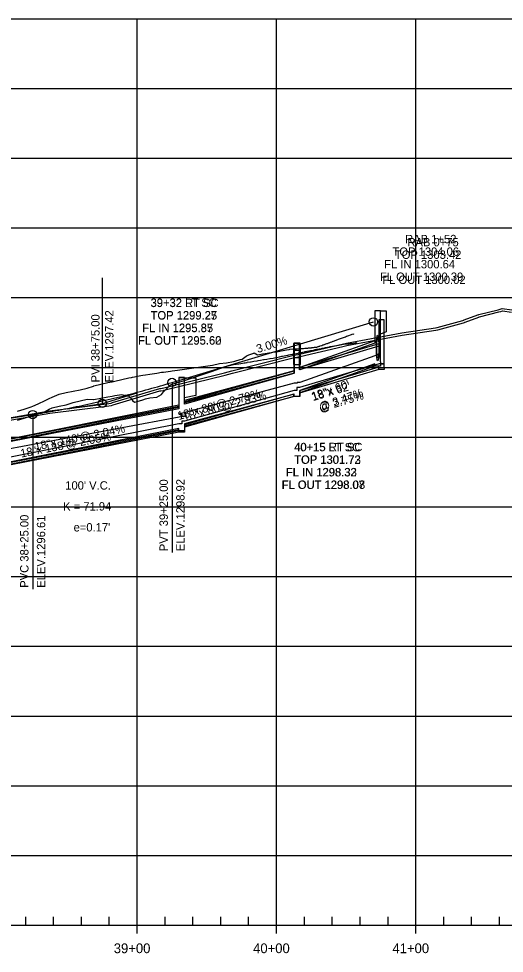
# Model space of a CAD drawing. Extents: x 670877 to 686811, y 705985 to 708501.
# Drawn here: x 685288 to 685636, y 707018 to 707688 of the extents above; entities that cross this region are included whole.
import ezdxf

# ---------------------------------------------------------------- set-up
doc = ezdxf.new("R2010")
doc.units = 0
for name, color, linetype in [('30', 7, 'Continuous'), ('37', 7, 'Continuous'), ('DRAINAGE_HGL LEFT', 7, 'Continuous'), ('DRAINAGE_HGL RIGHT', 7, 'Continuous'), ('Profile Drainage Annot Left', 7, 'Continuous'), ('Profile Drainage Annot Right', 7, 'Continuous'), ('R_Drainage Extensions_RIGHT', 7, 'Continuous'), ('R_Drainage LEFT', 7, 'Continuous'), ('R_Drainage RIGHT', 7, 'Continuous'), ('R_Exist Surface', 7, 'Continuous'), ('R_Profile Work Left', 7, 'Continuous'), ('R_Profile Work Right', 7, 'Continuous'), ('R_Vert Alg', 7, 'Continuous'), ('R_Vert Alg Annot', 7, 'Continuous')]:
    doc.layers.add(name, color=color, linetype=linetype)

msp = doc.modelspace()

# ---------------------------------------------------------------- linework, layer by layer
at = {"layer": '37'}
for p, q in [((684473.03, 707688.43), (686573.03, 707688.43)), ((685373.03, 707038.43), (685373.03, 707688.43)), ((685473.03, 707038.43), (685473.03, 707688.43)), ((685573.03, 707038.43), (685573.03, 707688.43)), ((684473.03, 707638.43), (686573.03, 707638.43)), ((684473.03, 707588.43), (686573.03, 707588.43)), ((684473.03, 707538.43), (686573.03, 707538.43)), ((684473.03, 707488.43), (686573.03, 707488.43)), ((684473.03, 707438.43), (686573.03, 707438.43)), ((684473.03, 707388.43), (686573.03, 707388.43)), ((684473.03, 707338.43), (686573.03, 707338.43)), ((684473.03, 707288.43), (686573.03, 707288.43)), ((684473.03, 707238.43), (686573.03, 707238.43)), ((684473.03, 707188.43), (686573.03, 707188.43)), ((684473.03, 707138.43), (686573.03, 707138.43)), ((684473.03, 707088.43), (686573.03, 707088.43)), ((685293.03, 707038.43), (685293.03, 707044.43)), ((685313.03, 707038.43), (685313.03, 707044.43)), ((685333.03, 707038.43), (685333.03, 707044.43)), ((685353.03, 707038.43), (685353.03, 707044.43)), ((685393.03, 707038.43), (685393.03, 707044.43)), ((685413.03, 707038.43), (685413.03, 707044.43)), ((685433.03, 707038.43), (685433.03, 707044.43)), ((685453.03, 707038.43), (685453.03, 707044.43)), ((685493.03, 707038.43), (685493.03, 707044.43)), ((685513.03, 707038.43), (685513.03, 707044.43)), ((685533.03, 707038.43), (685533.03, 707044.43)), ((685553.03, 707038.43), (685553.03, 707044.43)), ((685593.03, 707038.43), (685593.03, 707044.43)), ((685613.03, 707038.43), (685613.03, 707044.43)), ((685633.03, 707038.43), (685633.03, 707044.43)), ((684473.03, 707038.43), (686573.03, 707038.43)), ((685373.03, 707032.43), (685373.03, 707038.43)), ((685473.03, 707032.43), (685473.03, 707038.43)), ((685573.03, 707032.43), (685573.03, 707038.43))]:
    msp.add_line(p, q, dxfattribs=at)
at = {"layer": 'DRAINAGE_HGL LEFT'}
for points in [[(685263.31, 707399.22), (685310, 707407.29), (685350.89, 707412.31), (685354.24, 707412.73), (685355.27, 707413.16), (685389.24, 707423.35), (685389.91, 707423.25), (685391.03, 707423.48), (685391.17, 707423.64), (685435.74, 707434.43), (685440.97, 707435.87), (685484.53, 707446.95), (685489.61, 707447.94), (685520.16, 707454.98), (685523.19, 707455.67), (685559.03, 707462.39), (685563.01, 707463.18), (685587.1, 707466.75), (685588.11, 707466.94), (685588.32, 707467.01), (685606.77, 707472.02), (685607.18, 707472.18), (685607.55, 707472.34), (685607.76, 707472.44), (685617.53, 707476.03), (685617.73, 707476.1), (685618.13, 707476.31), (685632.15, 707479.78), (685633.61, 707480.15), (685634.93, 707480.62), (685641.88, 707479.61)], [(685548.38, 707441), (685550.38, 707441), (685550.38, 707441), (685546.6, 707441), (685489.4, 707424), (685487.48, 707424), (685487.48, 707421.93), (685485.57, 707421.93), (685407.03, 707399.93), (685405.03, 707399.93), (685405.03, 707398.05), (685403.03, 707398.05), (685258.95, 707369.45), (685260.95, 707369.45), (685260.95, 707368.25), (685262.95, 707368.25), (685115.94, 707349.55), (685117.94, 707349.55)]]:
    msp.add_lwpolyline(points, dxfattribs=at)
at = {"layer": 'DRAINAGE_HGL RIGHT'}
msp.add_lwpolyline([(685545.7, 707448.17), (685547.73, 707448.17), (685547.73, 707448.17), (685547.73, 707448.17), (685489.71, 707427.57), (685487.73, 707427.57), (685487.73, 707427.18), (685485.75, 707427.18), (685403.03, 707404.88), (685405.03, 707404.88), (685405.03, 707403.45), (685407.03, 707403.45), (685261.02, 707376.21), (685263.02, 707376.21), (685263.02, 707376.21), (685265.02, 707376.21), (685120.97, 707361.92), (685121.24, 707355.66), (685097.92, 707346.66)], dxfattribs=at)
at = {"layer": 'R_Drainage Extensions_RIGHT'}
msp.add_lwpolyline([(685547.73, 707479.03), (685551.73, 707479.03), (685551.73, 707464.03), (685547.73, 707462.36), (685547.73, 707479.03)], dxfattribs=at)
at = {"layer": 'R_Drainage LEFT'}
for points in [[(685550.38, 707472.63), (685546.38, 707472.63)], [(685546.38, 707472.63), (685546.38, 707453.56)], [(685550.38, 707438.63), (685550.38, 707472.63)], [(685489.48, 707455.63), (685485.48, 707455.63)], [(685485.48, 707455.63), (685485.48, 707434.11)], [(685489.48, 707436.65), (685489.48, 707455.63)], [(685546.38, 707455.23), (685489.48, 707438.32)], [(685546.38, 707453.56), (685489.48, 707436.65)], [(685546.38, 707438.56), (685489.48, 707421.65)], [(685546.38, 707436.9), (685546.38, 707438.56)], [(685550.38, 707438.63), (685550.38, 707436.9)], [(685407.03, 707431.13), (685403.03, 707431.13)], [(685403.03, 707431.13), (685403.03, 707409.63)], [(685485.48, 707435.77), (685407.03, 707413.8)], [(685485.48, 707434.11), (685407.03, 707412.13)], [(685407.03, 707412.13), (685407.03, 707431.13)], [(685546.38, 707436.9), (685489.48, 707419.99)], [(685550.38, 707436.9), (685546.38, 707436.9)], [(685485.48, 707419.11), (685407.03, 707397.13)], [(685485.48, 707417.44), (685407.03, 707395.46)], [(685485.48, 707417.44), (685485.48, 707419.11)], [(685489.48, 707417.44), (685485.48, 707417.44)], [(685489.48, 707421.65), (685489.48, 707417.44)], [(685403.03, 707411.3), (685262.95, 707383.49)], [(685403.03, 707409.63), (685262.95, 707381.82)], [(685407.03, 707397.13), (685407.03, 707392.96)], [(685403.03, 707394.63), (685262.95, 707366.82)], [(685403.03, 707392.96), (685262.95, 707365.16)], [(685403.03, 707392.96), (685403.03, 707394.63)], [(685407.03, 707392.96), (685403.03, 707392.96)]]:
    msp.add_lwpolyline(points, dxfattribs=at)
at = {"layer": 'R_Drainage RIGHT'}
for points in [[(685547.73, 707479.03), (685543.68, 707479.03)], [(685543.68, 707479.03), (685543.68, 707455.89)], [(685547.73, 707442.33), (685547.73, 707479.03)], [(685543.68, 707457.56), (685489.73, 707438.4)], [(685489.73, 707455.73), (685485.73, 707455.73)], [(685485.73, 707455.73), (685485.73, 707434.22)], [(685543.68, 707455.89), (685489.73, 707436.74)], [(685489.73, 707436.74), (685489.73, 707455.73)], [(685543.68, 707440.89), (685489.73, 707421.74)], [(685543.68, 707439.22), (685489.73, 707420.07)], [(685543.68, 707439.22), (685543.68, 707440.89)], [(685547.73, 707439.22), (685543.68, 707439.22)], [(685547.73, 707442.33), (685547.73, 707439.22)], [(685407.03, 707430.92), (685403.03, 707430.92)], [(685403.03, 707430.92), (685403.03, 707408.65)], [(685485.73, 707435.89), (685407.03, 707414.67)], [(685485.73, 707434.22), (685407.03, 707413.01)], [(685407.03, 707413.01), (685407.03, 707430.92)], [(685407.03, 707430.92), (685415.03, 707430.92), (685415.03, 707418.17), (685407.03, 707416.5), (685407.03, 707430.92)], [(685485.73, 707419.22), (685407.03, 707398.01)], [(685485.73, 707417.56), (685407.03, 707396.34)], [(685485.73, 707417.56), (685485.73, 707419.22)], [(685489.73, 707417.56), (685485.73, 707417.56)], [(685489.73, 707421.74), (685489.73, 707417.56)], [(685403.03, 707410.32), (685265.02, 707383.57)], [(685403.03, 707408.65), (685265.02, 707381.9)], [(685407.03, 707398.01), (685407.03, 707391.99)], [(685403.03, 707393.65), (685265.02, 707366.9)], [(685403.03, 707391.99), (685265.02, 707365.24)], [(685403.03, 707391.99), (685403.03, 707393.65)], [(685407.03, 707391.99), (685403.03, 707391.99)]]:
    msp.add_lwpolyline(points, dxfattribs=at)
for points in [[(685490.23, 707455.43), (685485.23, 707455.43), (685485.23, 707440.43), (685490.23, 707440.43)], [(685489.73, 707450.43), (685485.73, 707450.43), (685485.73, 707445.43), (685489.73, 707445.43)]]:
    msp.add_lwpolyline(points, close=True, dxfattribs=at)
for major_axis in [(0, 9.17), (0, 7.5)]:
    msp.add_ellipse((685545.7, 707452.33), major_axis=major_axis, ratio=0.1, dxfattribs=at)
at = {"layer": 'R_Exist Surface'}
msp.add_lwpolyline([(685263.59, 707397.57), (685310.24, 707405.64), (685351.09, 707410.65), (685354.67, 707411.1), (685355.83, 707411.58), (685389.37, 707421.65), (685389.96, 707421.56), (685391.92, 707421.96), (685392.08, 707422.14), (685436.16, 707432.81), (685441.4, 707434.26), (685484.9, 707445.32), (685489.96, 707446.31), (685520.53, 707453.35), (685523.53, 707454.03), (685559.35, 707460.75), (685563.3, 707461.54), (685587.38, 707465.1), (685588.54, 707465.32), (685588.8, 707465.41), (685607.29, 707470.43), (685607.83, 707470.64), (685608.26, 707470.83), (685608.41, 707470.9), (685618.12, 707474.46), (685618.4, 707474.57), (685618.72, 707474.73), (685632.55, 707478.16), (685634.1, 707478.55), (685635.1, 707478.91), (685641.64, 707477.96)], dxfattribs=at)
at = {"layer": 'R_Profile Work Left'}
for points in [[(685341.76, 707415.35), (685342.03, 707415.4), (685347.03, 707416.35), (685352.03, 707417.29), (685355.12, 707417.85), (685357.03, 707418.17), (685362.03, 707418.99), (685367.03, 707417.75), (685369.05, 707415.82), (685369.58, 707414.78), (685371.15, 707413.46), (685372.03, 707413.72), (685373.03, 707414.02), (685377.03, 707415.2), (685379.03, 707415.8), (685382.03, 707416.69), (685387.03, 707416.98), (685390.5, 707418.98), (685392.03, 707420.87), (685397.03, 707425.98), (685398.03, 707426.36), (685402.03, 707427.57), (685407.03, 707429.1), (685412.03, 707430.78), (685417.03, 707432.45), (685422.03, 707434.13), (685426.98, 707435.79), (685431.74, 707437.39), (685436.5, 707438.98), (685441.26, 707440.22), (685442.21, 707440.38), (685446, 707441.03), (685447.33, 707441.25), (685449.7, 707441.65), (685450.45, 707441.78), (685452.01, 707442.04), (685452.06, 707442.05), (685454.42, 707442.44), (685454.76, 707442.5), (685456.76, 707442.83), (685459.04, 707443.21), (685459.09, 707443.22), (685459.9, 707443.35), (685461.42, 707443.6), (685463.73, 707443.98), (685464.15, 707444.05), (685466.03, 707444.36), (685468.32, 707444.74), (685468.38, 707444.75), (685470.61, 707445.13), (685472.6, 707445.53), (685472.89, 707445.59), (685475.15, 707446.03), (685476.82, 707446.36), (685477.41, 707446.48), (685479.66, 707446.93), (685481.02, 707447.19), (685481.9, 707447.37), (685484.13, 707447.81), (685484.35, 707447.85), (685485.22, 707448.02), (685485.87, 707448.15), (685486.35, 707448.25), (685487.38, 707448.45), (685488.56, 707448.68), (685488.89, 707448.75), (685489.42, 707448.85), (685490.4, 707449.05), (685490.77, 707449.12), (685490.86, 707449.14), (685491.17, 707449.2), (685491.9, 707449.35), (685492.83, 707449.54), (685492.96, 707449.56), (685493.41, 707449.65), (685493.63, 707449.7), (685494.49, 707449.87), (685494.91, 707449.95), (685495.14, 707450), (685496.13, 707450.2), (685496.4, 707450.25), (685497.32, 707450.44), (685497.76, 707450.53), (685497.84, 707450.54), (685497.89, 707450.55), (685499.37, 707450.85), (685499.38, 707450.85), (685499.48, 707450.87), (685500.83, 707451.14), (685500.98, 707451.17), (685501.63, 707451.3), (685502.06, 707451.39), (685502.29, 707451.44), (685502.57, 707451.49), (685503.74, 707451.73), (685503.77, 707451.73), (685504.15, 707451.81), (685505.18, 707452.01), (685505.71, 707452.12), (685505.89, 707452.16), (685506.31, 707452.24), (685506.68, 707452.32), (685507.4, 707452.46), (685508.24, 707452.63), (685509.11, 707452.8), (685509.86, 707452.95), (685511.11, 707453.21), (685511.48, 707453.28), (685513.08, 707453.6), (685514.67, 707453.92), (685516.06, 707454.2), (685516.23, 707454.23), (685520.97, 707454.96), (685524.45, 707455.3), (685525.17, 707455.4), (685525.86, 707455.49), (685526.84, 707455.63), (685529.44, 707455.99), (685530.3, 707456.11), (685530.56, 707456.18)], [(685287.03, 707400.58), (685291.86, 707402.03), (685292.03, 707402.09), (685297.03, 707403.59), (685298.03, 707403.89), (685302.03, 707405.1), (685307.03, 707406.86), (685309.94, 707408.46), (685312.03, 707409.46), (685317.03, 707410.51), (685322.03, 707411.57)], [(685322.03, 707411.57), (685327.03, 707413.35), (685332.03, 707414.33), (685337.03, 707415.55), (685341.76, 707415.35)]]:
    msp.add_lwpolyline(points, dxfattribs=at)
at = {"layer": 'R_Profile Work Right'}
for points in [[(685459.36, 707447.51), (685462.03, 707447.93), (685462.09, 707447.94), (685463.03, 707448.08), (685464.81, 707448.37), (685467.53, 707448.8), (685468.03, 707448.87), (685470.25, 707449.22), (685472.96, 707449.65), (685473.03, 707449.66), (685475.42, 707450.06), (685477.53, 707450.44), (685477.83, 707450.5), (685480.23, 707450.96), (685481.99, 707451.31), (685482.62, 707451.44), (685484.98, 707451.62), (685486.41, 707451.68), (685487.32, 707451.72), (685489.65, 707451.85), (685489.88, 707451.86), (685490.6, 707451.91), (685491.13, 707451.95), (685491.53, 707451.98), (685492.37, 707452.04), (685493.33, 707452.12), (685493.59, 707452.14), (685494.02, 707452.18), (685494.8, 707452.25), (685495.09, 707452.27), (685495.17, 707452.28), (685495.42, 707452.3), (685496, 707452.36), (685496.73, 707452.42), (685496.83, 707452.43), (685497.18, 707452.47), (685497.36, 707452.49), (685498.02, 707452.56), (685498.35, 707452.6), (685498.53, 707452.62), (685499.3, 707452.71), (685499.51, 707452.73), (685500.21, 707452.82), (685500.55, 707452.86), (685500.62, 707452.87), (685500.65, 707452.87), (685501.78, 707453.01), (685501.79, 707453.02), (685501.87, 707453.03), (685502.92, 707453.32), (685503.04, 707453.36), (685503.54, 707453.53), (685503.87, 707453.64), (685504.06, 707453.71), (685504.27, 707453.78), (685505.18, 707454.09), (685505.2, 707454.1), (685505.5, 707454.2), (685506.3, 707454.48), (685506.71, 707454.62), (685506.85, 707454.67), (685507.15, 707454.77), (685507.41, 707454.86), (685507.91, 707455.04), (685508.51, 707455.25), (685509.11, 707455.46), (685509.6, 707455.64), (685510.44, 707455.94), (685510.69, 707456.02), (685511.76, 707456.41), (685512.83, 707456.8), (685513.78, 707457.15), (685513.9, 707457.19), (685518.32, 707458.84), (685521.86, 707460.17), (685522.59, 707460.44), (685523.29, 707460.7), (685524.29, 707461.07), (685526.91, 707462.05), (685527.78, 707462.38), (685528.5, 707462.34)], [(685437.03, 707441.59), (685442.03, 707442.73), (685443.03, 707442.97), (685447.03, 707443.96), (685448.42, 707444.34)], [(685448.42, 707444.34), (685451.16, 707446.54), (685452.03, 707446.88), (685453.84, 707447.58), (685453.89, 707447.61), (685456.63, 707448.67), (685457.03, 707448.83), (685459.36, 707447.51)], [(685287.03, 707407.02), (685291.86, 707408.52), (685292.03, 707408.58), (685297.03, 707410.18), (685298.03, 707410.55), (685302.03, 707412.41), (685307.03, 707414.73), (685309.94, 707416.08), (685312.03, 707417.05), (685317.03, 707419.29), (685322.03, 707420.33), (685327.03, 707421.37), (685332.03, 707422.41), (685337.03, 707423.45), (685341.76, 707424.98), (685342.03, 707425.08), (685347.03, 707426.36), (685352.03, 707427.48), (685355.12, 707428.17), (685357.03, 707428.59), (685362.03, 707429.71), (685367.03, 707430.82), (685369.05, 707431.27), (685369.58, 707431.39), (685371.15, 707431.74), (685372.03, 707431.93), (685373.03, 707432.15), (685377.03, 707432.83), (685379.03, 707433.15), (685382.03, 707433.62), (685387.03, 707434.38), (685390.5, 707434.88), (685392.03, 707435.1), (685397.03, 707435.82), (685398.03, 707435.96), (685402.03, 707436.53), (685407.03, 707437.25), (685412.03, 707437.96), (685417.03, 707438.68), (685422.03, 707439.39), (685427.03, 707440.11)], [(685427.03, 707440.11), (685432.03, 707441.16), (685437.03, 707441.59)]]:
    msp.add_lwpolyline(points, dxfattribs=at)
at = {"layer": 'R_Vert Alg'}
for p, q in [((685398.03, 707427.64), (685542.55, 707471.03)), ((685348.03, 707412.63), (685373.03, 707420.13)), ((685323.03, 707408.6), (685348.03, 707412.63)), ((685233.03, 707394.1), (685298.03, 707404.57))]:
    msp.add_line(p, q, dxfattribs=at)
msp.add_lwpolyline([(685298.03, 707404.57), (685300.11, 707404.91), (685302.2, 707405.26), (685304.28, 707405.61), (685306.36, 707405.96), (685308.45, 707406.33), (685310.53, 707406.7), (685312.61, 707407.07), (685314.7, 707407.45), (685316.78, 707407.84), (685318.86, 707408.23), (685320.95, 707408.63), (685323.03, 707409.04), (685325.11, 707409.45), (685327.2, 707409.86), (685329.28, 707410.29), (685331.36, 707410.72), (685333.45, 707411.15), (685335.53, 707411.59), (685337.61, 707412.04), (685339.7, 707412.49), (685341.78, 707412.95), (685343.86, 707413.42), (685345.95, 707413.89), (685350.11, 707414.85), (685352.2, 707415.34), (685354.28, 707415.84), (685356.36, 707416.34), (685358.45, 707416.85), (685360.53, 707417.36), (685362.61, 707417.88), (685364.7, 707418.41), (685366.78, 707418.94), (685368.86, 707419.48), (685370.95, 707420.02), (685373.03, 707420.57), (685375.11, 707421.13), (685377.2, 707421.69), (685379.28, 707422.26), (685381.36, 707422.83), (685383.45, 707423.41), (685385.53, 707424), (685387.61, 707424.59), (685389.7, 707425.19), (685391.78, 707425.79), (685393.86, 707426.4), (685395.95, 707427.02), (685398.03, 707427.64)], dxfattribs=at)
for centre in [(685542.55, 707471.03), (685398.03, 707427.64), (685348.03, 707412.63), (685298.03, 707404.57)]:
    msp.add_circle(centre, 3, dxfattribs=at)
at = {"layer": 'R_Vert Alg Annot'}
for p, q in [((685348.03, 707412.63), (685348.03, 707502.63)), ((685398.03, 707427.64), (685398.03, 707305.65)), ((685298.03, 707404.57), (685298.03, 707279.41))]:
    msp.add_line(p, q, dxfattribs=at)

# ---------------------------------------------------------------- texts
at = {"layer": '30'}
for s, p in [('39+00', (685356.22, 707018.43)), ('40+00', (685456.22, 707018.43)), ('41+00', (685556.22, 707018.43))]:
    msp.add_text(s, height=7, dxfattribs=at).set_placement(p)
at = {"layer": 'Profile Drainage Annot Left'}
for s, p in [('RAB 0+75', (685566.96, 707525.23)), ('TOP 1303.42', (685557.96, 707516.23)), ('FL OUT 1300.02', (685548.96, 707498.23)), ('39+32 LT SC', (685382.63, 707481.87)), ('TOP 1299.27', (685382.66, 707472.87)), ('FL IN 1295.87', (685376.66, 707463.87)), ('FL OUT 1295.62', (685373.67, 707454.87)), ('40+15 LT SC', (685485.57, 707378.24)), ('TOP 1301.72', (685485.61, 707369.24)), ('FL IN 1298.32', (685479.61, 707360.24)), ('FL OUT 1298.07', (685476.6, 707351.24))]:
    msp.add_text(s, height=6, dxfattribs=at).set_placement(p)
for s, rotation, p in [('18"x 62\'', 16.55245, (685499.35, 707414.25)), ('18"x 80\'@ 2.79%', 15.64833, (685402.87, 707400.64)), ('@ 2.75%', 16.55245, (685504.36, 707406.35)), ('18"x 140\'@ 2.04%', 11.5395, (685300, 707378.65))]:
    msp.add_text(s, height=6, rotation=rotation, dxfattribs=at).set_placement(p)
at = {"layer": 'Profile Drainage Annot Right'}
for s, p in [('RAB 1+52', (685565.29, 707527.43)), ('TOP 1304.06', (685556.29, 707518.43)), ('FL IN 1300.64', (685550.29, 707509.43)), ('FL OUT 1300.39', (685547.26, 707500.43)), ('39+32 RT SC', (685382.63, 707481.66)), ('TOP 1299.25', (685382.67, 707472.66)), ('FL IN 1295.85', (685376.67, 707463.66)), ('FL OUT 1295.60', (685373.71, 707454.66)), ('40+15 RT SC', (685485.82, 707378.34)), ('TOP 1301.73', (685485.86, 707369.34)), ('FL IN 1298.33', (685479.86, 707360.34)), ('FL OUT 1298.08', (685476.88, 707351.34))]:
    msp.add_text(s, height=6, dxfattribs=at).set_placement(p)
for s, rotation, p in [('18"x 60\'', 19.54929, (685499.22, 707414.47)), ('18"x 80\'@ 2.83%', 15.08626, (685406.82, 707399.66)), ('@ 3.47%', 19.54929, (685504.63, 707406.84)), ('18"x 138\'@ 2.05%', 10.96916, (685289.79, 707373.73))]:
    msp.add_text(s, height=6, rotation=rotation, dxfattribs=at).set_placement(p)
at = {"layer": 'R_Vert Alg Annot'}
for s, rotation, p in [('ELEV.1297.42', 90, (685356.03, 707427.63)), ('PVI 38+75.00', 90, (685346.03, 707427.63)), ('3.00%', 16.71118, (685459.5, 707448.71)), ('PVT 39+25.00', 90, (685395.03, 707306.65)), ('ELEV.1298.92', 90, (685407.03, 707306.65)), ('PVC 38+25.00', 90, (685295.03, 707280.41)), ('ELEV.1296.61', 90, (685307.03, 707280.41))]:
    msp.add_text(s, height=6, rotation=rotation, dxfattribs=at).set_placement(p)
for s, p in [("100' V.C.", (685321.41, 707350.78)), ('K = 71.94', (685319.87, 707335.78)), ("e=0.17'", (685327.41, 707320.78))]:
    msp.add_text(s, height=6, dxfattribs=at).set_placement(p)

doc.saveas('drawing.dxf')
